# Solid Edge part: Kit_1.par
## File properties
Author: bmolnar
Last saved by: bmolnar
Revision: 76
Sűrűség: 0,000 kg/m^3
Pontosság: 0,990
Username: bmolnar
Dokumentum tartalom típus: 0
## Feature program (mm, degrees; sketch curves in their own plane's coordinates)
base feature "unnamed BaseFeature 1"
sketch for "Furat_1" plane through (-18.15, 18.15, 0) normal (1, 0, 0) x-axis (0, 0, -1)
  hole centre (0, -13.85) bore radius 2.067
hole "Furat_1" nominal diameter 5 finite  ThreadDepth = 5 mm; StartChamferOffset = 0.5 mm; StartChamferAngle = 45 deg
sketch for "Furat_2" plane through (-11, 6.7, 11) normal (0, 1, 0) x-axis (0, 0, -1)
  hole centre (0, 0) bore radius 2.067
hole "Furat_2" nominal diameter 5
sketch for "unnamed Hole 1" plane through (-11, 6.7, 11) normal (0, 1, 0) x-axis (0, 0, -1)
  hole centre (22, 0) bore radius 2.067
hole "unnamed Hole 1"
sketch for "unnamed Hole 2" plane through (-11, 6.7, 11) normal (0, 1, 0) x-axis (0, 0, -1)
  hole centre (22, -22) bore radius 2.067
hole "unnamed Hole 2"
sketch for "unnamed Hole 3" plane through (-11, 6.7, 11) normal (0, 1, 0) x-axis (0, 0, -1)
  hole centre (0, -22) bore radius 2.067
hole "unnamed Hole 3"
pattern "unnamed Pattern 1" of "Furat_2", "unnamed Hole 1", "unnamed Hole 2", "unnamed Hole 3"
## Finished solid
Body 1: solid body, 238 faces, 596 edges, 372 vertices, 2 internal voids.
  Faces by surface: plane 121, cylinder 54, swept 43, cone 16, torus 4
  Edges by curve: line 361, circle 135, spline 90, curve on surface 5, intersection 4, ellipse 1
Bounding box of the edges (mm; curved faces can reach further): 36.300 x 11.800 x 36.300, from (-18.15, 0, -18.15) to (18.15, 11.8, 18.15).
Cylindrical faces by radius (mm): R0.2 x18, R0.4246 x1, R0.4865 x1, R2.067 x5, R3.75 x2, R4 x4, R4.1 x12, R4.5 x1, R5.45 x2, R5.55 x2, R11.25 x6
Conical faces (half-angle, radius in mm at the cone's reference point): 0.5 deg R4.5 x4, 45 deg R2.317 x2, 45 deg R2.367 x2, 45 deg R2.567 x1, 45 deg R4.25 x2, 45 deg R4.65 x1, 45 deg R5.3 x2, 45 deg R5.35 x2
Toroidal faces (ring radius, tube radius in mm): R3.8 r0.2 x2, R4.4 r0.4 x2
Planar faces by outward normal: +x 5, +y 14, +z 13, -x 7, -y 3, -z 15, oblique 64
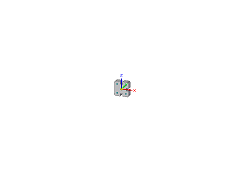
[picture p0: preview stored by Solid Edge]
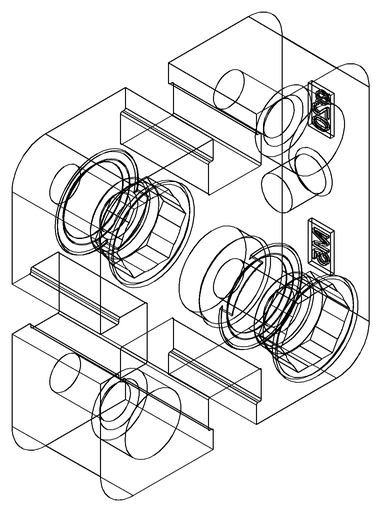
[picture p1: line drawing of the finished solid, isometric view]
